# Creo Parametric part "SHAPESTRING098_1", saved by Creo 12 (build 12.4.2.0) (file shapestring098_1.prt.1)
Units: Custom; MM, KILOGRAM, SECS

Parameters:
  PTC_WM_ITERATION = "0"
  PTC_WM_VERSION = "-.0"
  PTC_WM_LIFECYCLE_STATE = "In Work"
  PTC_WM_LIFECYCLE = "MO_CADDocument"
  PTC_WM_CREATED_BY = "Maximilian Roepper (Z0017RMS: MO)"
  PTC_WM_CREATED_ON = "18-Sep-26 11:36:42 AM"
  PTC_WM_MODIFIED_BY = "Maximilian Roepper (Z0017RMS: MO)"
  PTC_WM_MODIFIED_ON = "18-Sep-26 11:36:46 AM"
  PDMLINKNUMBER = "PDM000071454940"
  PTC_WM_NAME = "shapestring098_1.prt"
  PTC_WM_NUMBER = "PDM000071454940"

Other parameters: WEIGHT, WEIGHT_FACTOR, WEIGHT_ADD, _MASS_TEMP, _DIFF_TEMP, MC_ERRORS, SUPPLIER

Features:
  1. coordinate system
  2. datum plane "PRT_YZ"
  3. datum plane "PRT_XY"
  4. datum plane "PRT_XZ"
  5. coordinate system
  6. datum axis
  7. datum axis
  8. datum axis
  9. coordinate system
  10. imported feature
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
Other named items: PRT, SIEMENS_MO, DRW_VIEW_ORG, PRT_X, PRT_Y, PRT_Z, CS0, ROUGH_GROB

Layers: 00_STD_CSYS-KSYS, 01_STD_PLANES-EBENEN, 02_STD_AXES-ACHSEN, 03_STD_CSYS-KSYS, 24_IMPORT_FEAT-IMPORT_KE, INTFCLR

Surfaces: 1 plane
